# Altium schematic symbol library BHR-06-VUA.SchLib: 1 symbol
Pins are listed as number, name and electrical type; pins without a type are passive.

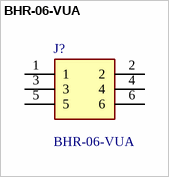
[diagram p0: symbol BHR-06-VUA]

## BHR-06-VUA
designator J?
Box Header, Vertical, 6 Pos; Manufacturer_Name: Adam Tech; Geometry.Height: 9.2mm
footprint SHDR6W64P254_2X3_1522X880X920P
pins: 1, 2, 3, 4, 5, 6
